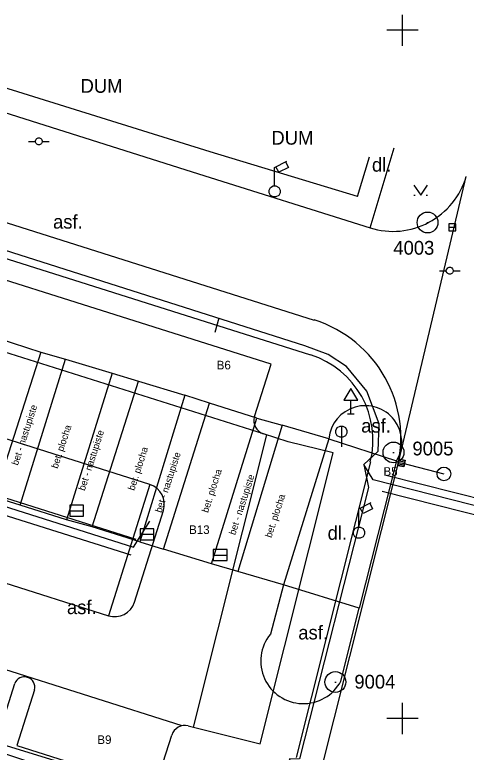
# Model space of a CAD drawing. Extents: x -733601 to -733291, y -1137892 to -1137187.
# Drawn here: x -733478.2 to -733445.4, y -1137552.5 to -1137498.9 of the extents above; entities that cross this region are included whole.
import ezdxf

# ---------------------------------------------------------------- set-up
doc = ezdxf.new("R2010")
doc.units = 0
for name, color, linetype in [('BP_NOVE_NAVRH', 7, 'Continuous'), ('BP_PBPP_pouzito_pro_map_podklady', 7, 'Continuous'), ('Default', 7, 'Continuous'), ('Krizky_Hektom_sit', 7, 'Continuous'), ('SIT_PROJ', 7, 'Continuous'), ('SIT_PUV_BUS', 7, 'Continuous')]:
    doc.layers.add(name, color=color, linetype=linetype)

# ---------------------------------------------------------------- blocks, each defined once
blk = doc.blocks.new('DOPRAVA_4$0$SYMB1230')
at = {"layer": 'Default'}
for p, q in [((-0.1, -0.329897), (-0.1, -0.020619)), ((-0.1, -0.325773), (-0.1, -0.329897)), ((0, -0.020619), (0, -0.329897)), ((0.1, -0.020619), (0.1, -0.329897))]:
    blk.add_line(p, q, dxfattribs=at)
for points in [[(-0.2, 0), (0.2, 0), (0.2, -0.35), (-0.2, -0.35)], [(-0.182831, -0.020619), (0.181696, -0.020619), (0.181696, -0.329897), (-0.182831, -0.329897)]]:
    blk.add_lwpolyline(points, close=True, dxfattribs=at)

msp = doc.modelspace()

# ---------------------------------------------------------------- linework, layer by layer
at = {"layer": 'BP_NOVE_NAVRH'}
msp.add_line((-733448.231, -1137513.963), (-733448.131, -1137513.963), dxfattribs=at)
msp.add_circle((-733448.181, -1137513.963), 0.756, dxfattribs=at)
at = {"layer": 'BP_PBPP_pouzito_pro_map_podklady'}
for p, q in [((-733450.706, -1137530.671), (-733450.606, -1137530.671)), ((-733454.926, -1137547.353), (-733454.826, -1137547.353))]:
    msp.add_line(p, q, dxfattribs=at)
for centre in [(-733450.656, -1137530.671), (-733454.876, -1137547.353)]:
    msp.add_circle(centre, 0.756, dxfattribs=at)
at = {"layer": 'Krizky_Hektom_sit'}
for p, q in [((-733450, -1137501.131), (-733450, -1137498.869)), ((-733448.869, -1137500), (-733451.131, -1137500)), ((-733450, -1137551.131), (-733450, -1137548.869)), ((-733448.869, -1137550), (-733451.131, -1137550))]:
    msp.add_line(p, q, dxfattribs=at)
at = {"layer": 'SIT_PROJ'}
for p, q in [((-733460.095, -1137529.321), (-733493.227, -1137518.841)), ((-733468.341, -1137533.006), (-733496.944, -1137523.958)), ((-733465.187, -1137550.636), (-733459.855, -1137529.397)), ((-733499.96, -1137533.492), (-733471.356, -1137542.54)), ((-733466.004, -1137550.526), (-733507.966, -1137537.253)), ((-733479.441, -1137551.52), (-733478.159, -1137547.468))]:
    msp.add_line(p, q, dxfattribs=at)
for points in [[(-733472.116, -1137618.354), (-733450.389, -1137531.821), (-733445.369, -1137510.61)], [(-733488.129, -1137511.014), (-733456.405, -1137521.049)], [(-733460.747, -1137528.066), (-733459.541, -1137524.252), (-733494.007, -1137513.35)], [(-733487.24, -1137513.917), (-733456.681, -1137523.583)], [(-733452.807, -1137531.541), (-733451.767, -1137530.574), (-733451.693, -1137528.596), (-733452.588, -1137526.208), (-733454.078, -1137524.418), (-733455.407, -1137523.545), (-733457.093, -1137522.916), (-733483.255, -1137514.587), (-733483.623, -1137515.683)], [(-733463.347, -1137520.925), (-733463.635, -1137521.963)], [(-733452.807, -1137531.541), (-733452.473, -1137533.224), (-733457.478, -1137552.932), (-733458.231, -1137552.948), (-733457.677, -1137553.487), (-733458.16, -1137554.567), (-733458.792, -1137555.404), (-733459.851, -1137556.172), (-733461, -1137556.688), (-733462.364, -1137556.956), (-733463.762, -1137556.963), (-733467.652, -1137556.198), (-733471.45, -1137555.042), (-733482.168, -1137551.478), (-733485.798, -1137550.329), (-733497.445, -1137546.837), (-733510.353, -1137542.814), (-733504.974, -1137526.312), (-733469.528, -1137537.558), (-733468.34, -1137535.665)], [(-733465.56, -1137550.543), (-733460.338, -1137551.854), (-733455.029, -1137530.71), (-733458.293, -1137529.891), (-733460.095, -1137529.321)], [(-733457.917, -1137622.364), (-733458.777, -1137620.095), (-733456.339, -1137614.218), (-733457.273, -1137613.333), (-733455.913, -1137612.939), (-733454.69, -1137608.9), (-733452.562, -1137600.661), (-733449.967, -1137590.732), (-733451.007, -1137589.721), (-733449.679, -1137589.475), (-733444.067, -1137566.075), (-733444.902, -1137565.405), (-733443.754, -1137565.269), (-733437.875, -1137541.673), (-733438.793, -1137541.042), (-733437.71, -1137541.027), (-733436.525, -1137536.63), (-733452.133, -1137532.662), (-733452.807, -1137531.541)], [(-733452.337, -1137531.363), (-733457.726, -1137552.828)], [(-733450.074, -1137531.434), (-733446.992, -1137532.235)], [(-733451.176, -1137532.326), (-733441.226, -1137534.835)], [(-733482.363, -1137532.866), (-733469.375, -1137536.976)], [(-733468.341, -1137533.006), (-733471.356, -1137542.54)], [(-733451.469, -1137533.49), (-733441.52, -1137535.998)], [(-733482.725, -1137534.01), (-733469.737, -1137538.12)], [(-733469.474, -1137541.562), (-733467.363, -1137534.888)], [(-733476.729, -1137547.92), (-733478.011, -1137551.972), (-733468, -1137555.139), (-733466.757, -1137551.211)]]:
    msp.add_lwpolyline(points, dxfattribs=at)
msp.add_circle((-733446.992, -1137532.236), 0.5, dxfattribs=at)
for centre, radius, start, end in [((-733459.119, -1137529.629), 9, 345.9059, 72.4471), ((-733458.642, -1137529.781), 6.5, 345.9059, 72.4471), ((-733459.794, -1137528.367), 1, 162.4471, 252.447), ((-733468.793, -1137534.436), 1.5, 342.4471, 72.4471), ((-733470.904, -1137541.11), 1.5, 252.4471, 342.4471), ((-733477.456, -1137547.731), 0.751, 345.4042, 159.49), ((-733465.804, -1137551.513), 1, 75.906, 162.4471)]:
    msp.add_arc(centre, radius, start, end, dxfattribs=at)
at = {"layer": 'SIT_PUV_BUS'}
for p, q in [((-733463.96, -1137508.84), (-733482.5, -1137503.04)), ((-733481.95, -1137504.99), (-733464.81, -1137510.43)), ((-733477.16, -1137508.07), (-733476.66, -1137508.07)), ((-733476.66, -1137508.02), (-733476.61, -1137507.92)), ((-733476.66, -1137508.12), (-733476.66, -1137508.02)), ((-733476.61, -1137508.22), (-733476.66, -1137508.12)), ((-733476.61, -1137507.92), (-733476.56, -1137507.87)), ((-733476.56, -1137507.87), (-733476.46, -1137507.82)), ((-733476.46, -1137507.82), (-733476.36, -1137507.82)), ((-733476.36, -1137507.82), (-733476.26, -1137507.87)), ((-733476.26, -1137507.87), (-733476.21, -1137507.92)), ((-733476.21, -1137507.92), (-733476.16, -1137508.02)), ((-733476.16, -1137508.12), (-733476.21, -1137508.22)), ((-733476.16, -1137508.02), (-733476.16, -1137508.12)), ((-733476.16, -1137508.07), (-733475.66, -1137508.07)), ((-733476.56, -1137508.27), (-733476.61, -1137508.22)), ((-733476.46, -1137508.32), (-733476.56, -1137508.27)), ((-733476.36, -1137508.32), (-733476.46, -1137508.32)), ((-733476.26, -1137508.27), (-733476.36, -1137508.32)), ((-733476.21, -1137508.22), (-733476.26, -1137508.27)), ((-733452.35, -1137514.36), (-733450.6, -1137508.53)), ((-733453.27, -1137512.07), (-733463.96, -1137508.84)), ((-733453.27, -1137512.07), (-733452.41, -1137509.2)), ((-733459.29, -1137509.96), (-733458.39, -1137509.51)), ((-733458.49, -1137509.56), (-733458.29, -1137509.96)), ((-733459.29, -1137511.31), (-733459.29, -1137509.96)), ((-733458.99, -1137510.31), (-733459.19, -1137509.91)), ((-733458.29, -1137509.96), (-733458.99, -1137510.31)), ((-733464.81, -1137510.43), (-733452.35, -1137514.36)), ((-733459.69, -1137511.61), (-733459.59, -1137511.41)), ((-733459.59, -1137511.41), (-733459.39, -1137511.31)), ((-733459.39, -1137511.31), (-733459.19, -1137511.31)), ((-733459.19, -1137511.31), (-733458.99, -1137511.41)), ((-733458.99, -1137511.41), (-733458.89, -1137511.61)), ((-733449.18, -1137511.24), (-733448.68, -1137511.99)), ((-733448.68, -1137511.99), (-733448.18, -1137511.24)), ((-733459.69, -1137511.81), (-733459.69, -1137511.61)), ((-733459.59, -1137512.01), (-733459.69, -1137511.81)), ((-733458.89, -1137511.81), (-733458.99, -1137512.01)), ((-733458.89, -1137511.61), (-733458.89, -1137511.81)), ((-733459.39, -1137512.11), (-733459.59, -1137512.01)), ((-733459.19, -1137512.11), (-733459.39, -1137512.11)), ((-733458.99, -1137512.01), (-733459.19, -1137512.11)), ((-733449.18, -1137511.99), (-733449.08, -1137511.99)), ((-733448.28, -1137511.99), (-733448.18, -1137511.99)), ((-733446.14, -1137514.07), (-733446.64, -1137514.07)), ((-733446.64, -1137514.07), (-733446.64, -1137514.57)), ((-733446.14, -1137514.57), (-733446.14, -1137514.07)), ((-733446.14, -1137514.32), (-733446.64, -1137514.32)), ((-733446.64, -1137514.57), (-733446.14, -1137514.57)), ((-733446.77, -1137517.32), (-733446.72, -1137517.27)), ((-733446.72, -1137517.27), (-733446.62, -1137517.22)), ((-733446.62, -1137517.22), (-733446.52, -1137517.22)), ((-733446.52, -1137517.22), (-733446.42, -1137517.27)), ((-733446.42, -1137517.27), (-733446.37, -1137517.32)), ((-733447.32, -1137517.47), (-733446.82, -1137517.47)), ((-733446.82, -1137517.42), (-733446.77, -1137517.32)), ((-733446.82, -1137517.52), (-733446.82, -1137517.42)), ((-733446.77, -1137517.62), (-733446.82, -1137517.52)), ((-733446.72, -1137517.67), (-733446.77, -1137517.62)), ((-733446.62, -1137517.72), (-733446.72, -1137517.67)), ((-733446.52, -1137517.72), (-733446.62, -1137517.72)), ((-733446.42, -1137517.67), (-733446.52, -1137517.72)), ((-733446.37, -1137517.62), (-733446.42, -1137517.67)), ((-733446.37, -1137517.32), (-733446.32, -1137517.42)), ((-733446.32, -1137517.52), (-733446.37, -1137517.62)), ((-733446.32, -1137517.42), (-733446.32, -1137517.52)), ((-733446.32, -1137517.47), (-733445.82, -1137517.47)), ((-733479.77, -1137522.27), (-733476.26, -1137523.39)), ((-733476.26, -1137523.39), (-733479.65, -1137533.93)), ((-733476.26, -1137523.39), (-733474.48, -1137523.89)), ((-733477.76, -1137534.51), (-733474.48, -1137523.89)), ((-733474.48, -1137523.89), (-733471.08, -1137524.92)), ((-733471.08, -1137524.92), (-733474.4, -1137535.56)), ((-733471.08, -1137524.92), (-733469.18, -1137525.5)), ((-733472.54, -1137536.08), (-733469.18, -1137525.5)), ((-733469.18, -1137525.5), (-733465.82, -1137526.51)), ((-733453.75, -1137526.02), (-733454.25, -1137526.87)), ((-733453.25, -1137526.87), (-733453.75, -1137526.02)), ((-733465.82, -1137526.51), (-733469.08, -1137537.17)), ((-733464.02, -1137527.08), (-733465.82, -1137526.51)), ((-733454.25, -1137526.87), (-733453.25, -1137526.87)), ((-733453.75, -1137527.87), (-733453.75, -1137526.87)), ((-733467.35, -1137537.7), (-733464.02, -1137527.08)), ((-733460.59, -1137528.17), (-733464.02, -1137527.08)), ((-733454, -1137527.87), (-733453.5, -1137527.87)), ((-733463.86, -1137538.76), (-733460.59, -1137528.17)), ((-733460.59, -1137528.17), (-733458.74, -1137528.69)), ((-733458.74, -1137528.69), (-733461.96, -1137539.33)), ((-733455.35, -1137529.68), (-733458.74, -1137528.69)), ((-733454.84, -1137529.07), (-733454.74, -1137528.87)), ((-733454.84, -1137529.27), (-733454.84, -1137529.07)), ((-733454.74, -1137528.87), (-733454.54, -1137528.77)), ((-733454.54, -1137528.77), (-733454.34, -1137528.77)), ((-733454.44, -1137528.77), (-733454.44, -1137530.27)), ((-733454.34, -1137528.77), (-733454.14, -1137528.87)), ((-733454.14, -1137528.87), (-733454.04, -1137529.07)), ((-733454.04, -1137529.07), (-733454.04, -1137529.27)), ((-733454.74, -1137529.47), (-733454.84, -1137529.27)), ((-733454.54, -1137529.57), (-733454.74, -1137529.47)), ((-733454.34, -1137529.57), (-733454.54, -1137529.57)), ((-733454.14, -1137529.47), (-733454.34, -1137529.57)), ((-733454.04, -1137529.27), (-733454.14, -1137529.47)), ((-733455.35, -1137529.68), (-733458.65, -1137540.3)), ((-733455.35, -1137529.68), (-733450.43, -1137531.29)), ((-733450.43, -1137531.29), (-733453.14, -1137541.98)), ((-733477.76, -1137534.51), (-733479.65, -1137533.93)), ((-733453.17, -1137534.76), (-733452.27, -1137534.31)), ((-733452.37, -1137534.36), (-733452.17, -1137534.76)), ((-733474.4, -1137535.56), (-733477.76, -1137534.51)), ((-733473.16, -1137534.51), (-733474.16, -1137534.51)), ((-733474.16, -1137534.51), (-733474.16, -1137535.31)), ((-733474.16, -1137534.91), (-733473.16, -1137534.91)), ((-733473.16, -1137535.31), (-733473.16, -1137534.51)), ((-733453.17, -1137536.11), (-733453.17, -1137534.76)), ((-733452.87, -1137535.11), (-733453.07, -1137534.71)), ((-733452.17, -1137534.76), (-733452.87, -1137535.11)), ((-733474.16, -1137535.31), (-733473.16, -1137535.31)), ((-733472.54, -1137536.08), (-733474.4, -1137535.56)), ((-733469.08, -1137537.17), (-733472.54, -1137536.08)), ((-733468.05, -1137536.22), (-733469.05, -1137536.22)), ((-733469.05, -1137536.22), (-733469.05, -1137537.02)), ((-733468.05, -1137537.02), (-733468.05, -1137536.22)), ((-733453.57, -1137536.41), (-733453.47, -1137536.21)), ((-733453.57, -1137536.61), (-733453.57, -1137536.41)), ((-733453.47, -1137536.21), (-733453.27, -1137536.11)), ((-733453.27, -1137536.11), (-733453.07, -1137536.11)), ((-733453.07, -1137536.11), (-733452.87, -1137536.21)), ((-733452.87, -1137536.21), (-733452.77, -1137536.41)), ((-733452.77, -1137536.41), (-733452.77, -1137536.61)), ((-733469.05, -1137536.62), (-733468.05, -1137536.62)), ((-733469.05, -1137537.02), (-733468.05, -1137537.02)), ((-733453.47, -1137536.81), (-733453.57, -1137536.61)), ((-733453.27, -1137536.91), (-733453.47, -1137536.81)), ((-733453.07, -1137536.91), (-733453.27, -1137536.91)), ((-733452.87, -1137536.81), (-733453.07, -1137536.91)), ((-733452.77, -1137536.61), (-733452.87, -1137536.81)), ((-733469.08, -1137537.17), (-733467.35, -1137537.7)), ((-733463.86, -1137538.76), (-733467.35, -1137537.7)), ((-733462.74, -1137537.73), (-733463.74, -1137537.73)), ((-733463.74, -1137537.73), (-733463.74, -1137538.53)), ((-733463.74, -1137538.13), (-733462.74, -1137538.13)), ((-733462.74, -1137538.53), (-733462.74, -1137537.73)), ((-733463.74, -1137538.53), (-733462.74, -1137538.53)), ((-733461.96, -1137539.33), (-733463.86, -1137538.76)), ((-733458.65, -1137540.3), (-733461.96, -1137539.33)), ((-733458.65, -1137540.3), (-733459.59, -1137543.87)), ((-733453.14, -1137541.98), (-733458.65, -1137540.3)), ((-733454.47, -1137547.29), (-733453.14, -1137541.98)), ((-733479.43, -1137551.77), (-733466.01, -1137555.88))]:
    msp.add_line(p, q, dxfattribs=at)
for centre, radius, start, end in [((-733450.7, -1137509.06), 5.547, 252.6894, 343.7366), ((-733452.71, -1137529.93), 2.656, 329.2312, 174.4862), ((-733457.2, -1137545.83), 3.093, 140.7585, 331.691)]:
    msp.add_arc(centre, radius, start, end, dxfattribs=at)

# ---------------------------------------------------------------- block references
at = {"layer": 'SIT_PROJ', "xscale": 1.25, "yscale": 1.2500000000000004, "rotation": 78.19096299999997}
msp.add_blockref('DOPRAVA_4$0$SYMB1230', (-733450.288, -1137531.389), dxfattribs=at)

# ---------------------------------------------------------------- texts
at = {"layer": 'BP_NOVE_NAVRH'}
msp.add_text('4003', height=1, dxfattribs=at).set_placement((-733450.666, -1137516.303))
at = {"layer": 'BP_PBPP_pouzito_pro_map_podklady'}
for s, p in [('9005', (-733449.28, -1137530.887)), ('9004', (-733453.495, -1137547.832))]:
    msp.add_text(s, height=1, dxfattribs=at).set_placement(p)
at = {"layer": 'SIT_PROJ'}
for s, p in [('B6', (-733463.492, -1137524.637)), ('B5', (-733451.381, -1137532.367)), ('B13', (-733465.496, -1137536.597)), ('B9', (-733472.16, -1137551.856))]:
    msp.add_text(s, height=0.625, rotation=360, dxfattribs=at).set_placement(p)
at = {"layer": 'SIT_PUV_BUS'}
for s, p in [('DUM', (-733473.38, -1137504.54)), ('DUM', (-733459.52, -1137508.31)), ('dl.', (-733452.22, -1137510.27)), ('asf.', (-733475.38, -1137514.41)), ('asf.', (-733453, -1137529.23)), ('dl.', (-733455.44, -1137537.02)), ('asf.', (-733474.37, -1137542.42)), ('asf.', (-733457.57, -1137544.26))]:
    msp.add_text(s, height=1, dxfattribs=at).set_placement(p)
for s, p in [('bet - nastupiste', (-733477.93, -1137531.65)), ('bet. plocha', (-733475.05, -1137531.88)), ('bet - nastupiste', (-733473.08, -1137533.49)), ('bet. plocha', (-733469.48, -1137533.48)), ('bet - nastupiste', (-733467.51, -1137535.09)), ('bet. plocha', (-733464.12, -1137535.09)), ('bet - nastupiste', (-733462.15, -1137536.71)), ('bet. plocha', (-733459.52, -1137536.91))]:
    msp.add_text(s, height=0.5, rotation=72, dxfattribs=at).set_placement(p)

doc.saveas('drawing.dxf')
